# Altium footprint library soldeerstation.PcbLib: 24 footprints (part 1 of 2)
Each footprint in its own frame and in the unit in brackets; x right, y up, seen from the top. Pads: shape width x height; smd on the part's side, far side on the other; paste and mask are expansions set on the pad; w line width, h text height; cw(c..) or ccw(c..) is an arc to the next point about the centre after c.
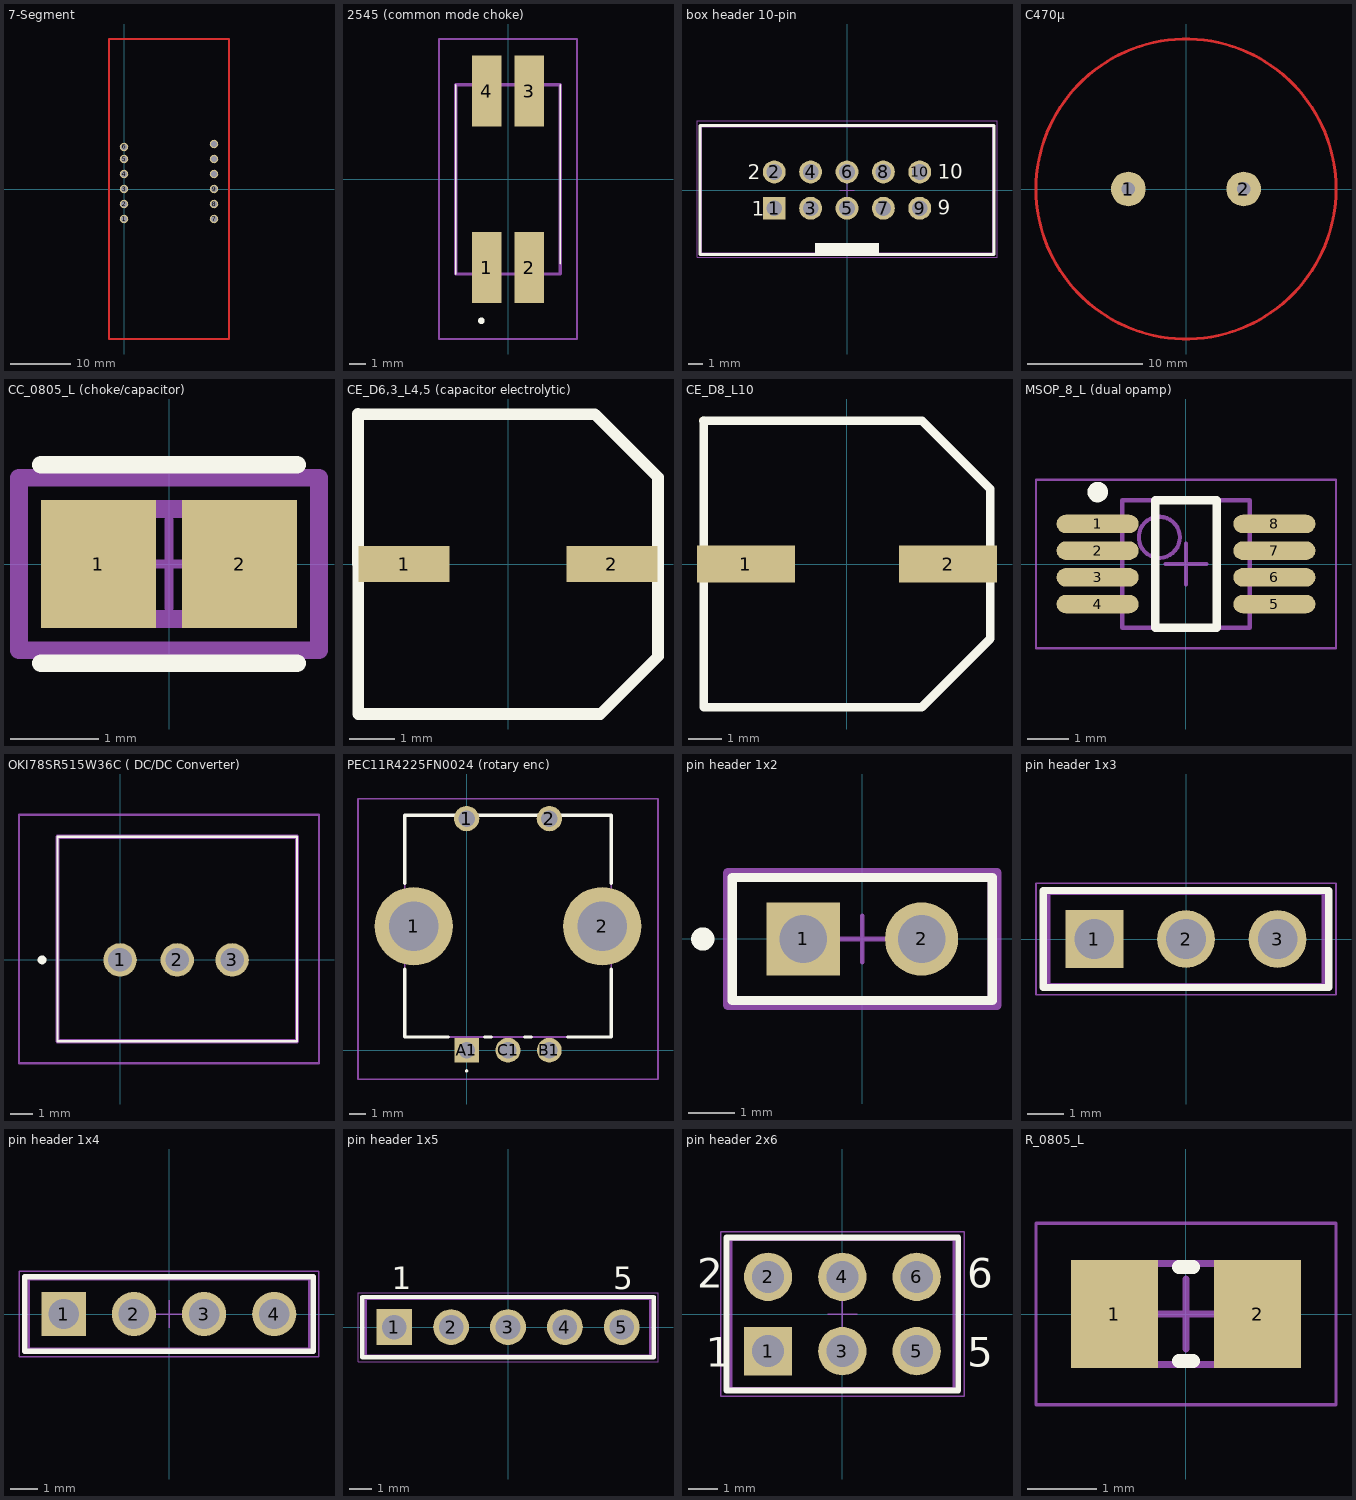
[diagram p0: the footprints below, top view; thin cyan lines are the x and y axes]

## 7-Segment [mm]
pads (12):
  round 1.425 hole 0.95: 1(0,-5) 2(0,-2.5) 3(0,0) 4(0,2.5) 5(0,5) 6(0,7) 7(15,-5) 8(15,-2.5) 9(15,0) 10(15,2.5) 11(15,5) 12(15,7.5)
Top Layer:
  lines w0.254: -2.5,-25 -2.5,15 -2.5,25 17.5,25 17.5,-25 -2.5,-25

## 2545 (common mode choke) [mm]
pads (4):
  rect 1.78x4.27 smd: 1(-1.27,-5.305) 2(1.27,-5.305) 3(1.27,5.305) 4(-1.27,5.305)
Top Overlay:
  lines w0.1: -3.15,-5.69 -3.15,5.69 ; 3.15,-5.08 3.15,5.69
  lines w0.2: -1.7,-8.5 cw(c-1.6,-8.5) -1.5,-8.5 cw(c-1.6,-8.5) -1.7,-8.5
Mechanical 13:
  lines w0.2: -3.15,-5.69 3.15,-5.69 3.15,5.69 -3.15,5.69 -3.15,-5.69
Mechanical 15:
  lines w0.1: -4.15,-9.6 4.15,-9.6 4.15,8.44 -4.15,8.44 -4.15,-9.6
3D body "CM2545X171R-10.stp": height 9.6, standoff 0, extent -3.15,-7.262 3.15,7.262

## box header 10-pin [mm] "10 pins, straight, gold plating"
height 9.1
pads (10):
  rect 1.6x1.6 hole 1.1: 1(-5.08,-1.27)
  round 1.6 hole 1.1: 2(-5.08,1.27) 3(-2.54,-1.27) 4(-2.54,1.27) 5(0,-1.27) 6(0,1.27) 7(2.54,-1.27) 8(2.54,1.27) 9(5.08,-1.27) 10(5.08,1.27)
Top Overlay:
  rectangle: -2.25,-4.5 2.25,-3.7
  lines w0.2: -10.28,-4.5 -10.28,4.5 10.28,4.5 10.28,-4.5 -10.28,-4.5
  text "9" at 6.34,-1.74 h1.02
  text "10" at 6.34,0.8 h1.02
  text "2" at -6.94,0.74 h1.02
  text "1" at -6.64,-1.8 h1.02
Mechanical 13:
  rectangle: -2.25,-4.425 2.25,-3.7
  lines w0.1: -10.18,-4.425 10.18,-4.425 10.18,4.425 -10.18,4.425 -10.18,-4.425
Mechanical 15:
  lines w0.05: -0.5,0 0.5,0 ; 0,-0.5 0,0.5 ; -10.48,-4.7 -10.48,4.85 10.48,4.85 10.48,-4.7 -10.48,-4.7
3D body "61201021621.stp": height 9.13, standoff -2.98, extent -10.18,-4.425 10.18,4.75

## C470µ [mm]
pads (2):
  round 3 hole 1.2: 1(-5,0) 2(5,0)
Top Layer:
  circle w0.254: c0,0 r13

## CC_0805_L (choke/capacitor) [mm]
pads (2):
  rect 1.305x1.456 smd paste+0 mask+0: 1(-0.801,0) 2(0.801,0)
Top Overlay:
  lines w0.2: -1.453,-1.128 1.453,-1.128 ; -1.453,1.128 1.453,1.128
Top 3D Body:
  lines w0.2: -1,-0.625 1,-0.625 1,0.625 -1,0.625 -1,-0.625
Top Courtyard:
  lines w0.2: -1.703,-0.978 1.703,-0.978 1.703,0.978 -1.703,0.978 -1.703,-0.978
Top Assembly:
  lines w0.2: -1.703,-0.978 1.703,-0.978 1.703,0.978 -1.703,0.978 -1.703,-0.978
  text ".Designator" at 0,0.188 h1
Top Component Center:
  lines w0.1: -0.5,0 0.5,0 ; 0,-0.5 0,0.5
3D body "Cap_KEMET_C0805C472J3HAC_eec.STEP": height 0.25, standoff 0, extent -1.703,-0.978 1.703,0.978

## CE_D6,3_L4,5 (capacitor electrolytic) [mm]
pads (2):
  rect 2x0.8 smd: 1(-2.286,0) 2(2.286,0)
Top Overlay:
  lines w0.254: -3.302,0.002 -3.3,0 -3.3,-3.3 2.034,-3.3 3.3,-2.034 3.3,1.907 1.907,3.3 0,3.3 -3.3,3.3 -3.302,3.302 -3.302,0.002

## CE_D8_L10 [mm]
pads (2):
  rect 2.9x1.1 smd: 1(-3,0) 2(3,0)
Top Layer:
  lines w0.254: -4.259,4.25 -4.25,4.241
Top Overlay:
  lines w0.254: -4.259,4.25 2.227,4.25 4.25,2.227 4.25,0 4.25,-2.218 2.218,-4.25 -4.25,-4.25 -4.25,4.241

## MSOP_8_L (dual opamp) [mm] "TSOP, 8-Leads, Body 3x3mm, Pitch 0.65mm, IPC Low Density"
height 1.1
pads (8):
  oval 2x0.45 smd: 1(-2.15,0.975) 2(-2.15,0.325) 3(-2.15,-0.325) 4(-2.15,-0.975) 5(2.15,-0.975) 6(2.15,-0.325) 7(2.15,0.325) 8(2.15,0.975)
Top Overlay:
  circle w0.25: c-2.15,1.75 r0.125
  lines w0.2: -0.75,-1.55 -0.75,1.55 0.75,1.55 0.75,-1.55 -0.75,-1.55
Mechanical 13:
  circle w0.1: c-0.65,0.65 r0.5
  lines w0.1: -1.55,-1.55 -1.55,1.55 1.55,1.55 1.55,-1.55 -1.55,-1.55
Mechanical 15:
  lines w0.05: -3.65,-2.05 -3.65,2.05 3.65,2.05 3.65,-2.05 -3.65,-2.05
  lines w0.1: -0.5,0 0.5,0 ; 0,-0.5 0,0.5
3D body: height 1.1, standoff 0, extent -1.55,-1.55 1.55,1.55

## OKI78SR515W36C ( DC/DC Converter) [mm]
pads (3):
  round 1.519 hole 1.08: 1(0,0) 2(2.6,0) 3(5.1,0)
Top Overlay:
  lines w0.1: -2.85,-3.7 8.05,-3.7 8.05,5.6 -2.85,5.6 -2.85,-3.7
  lines w0.3: -3.6,0 cw(c-3.55,0) -3.5,0 cw(c-3.55,0) -3.6,0
Mechanical 13:
  lines w0.2: -2.85,-3.7 8.05,-3.7 8.05,5.6 -2.85,5.6 -2.85,-3.7
Mechanical 15:
  lines w0.1: -4.6,-4.7 9.05,-4.7 9.05,6.6 -4.6,6.6 -4.6,-4.7
3D body "OKI-78SR-5_1.5-W36-C.stp": height 16.6, standoff -5, extent -2.85,-3.7 8.05,5.6

## PEC11R4225FN0024 (rotary enc) [mm]
pads (7):
  round 4.74 hole 3: 1(-3.2,7.5) 2(8.2,7.5)
  round 1.524 hole 1: 1(0,14) 2(5,14)
  rect 1.5x1.5 hole 1: A1(0,0)
  round 1.5 hole 1: B1(5,0) C1(2.5,0)
Top Overlay:
  lines w0.1: 0,-1.3 ccw(c0,-1.25) 0,-1.2 ccw(c0,-1.25) 0,-1.3
  lines w0.2: -3.75,4.9 -3.75,0.8 -1.1,0.8 ; -3.75,10.1 -3.75,14.2 8.75,14.2 8.75,10.1 ; 1.1,0.8 1.5,0.8 ; 3.5,0.8 3.9,0.8 ; 6.1,0.8 8.75,0.8 8.75,4.9
Mechanical 13:
  lines w0.1: -3.75,0.8 -3.75,14.2 8.75,14.2 8.75,0.8 -3.75,0.8
Mechanical 15:
  lines w0.1: -6.57,-1.75 -6.57,15.2 11.57,15.2 11.57,-1.75 -6.57,-1.75
3D body "PEC11R-4225F-N0024.stp": height 31.6, standoff -5, extent -4.668,-0.399 9.68,14.2

## pin header 1x2 [mm]
pads (2):
  rect 1.57x1.57 hole 1.02 paste-1000 mask+0: 1(-1.27,0)
  round 1.57 hole 1.02 paste-1000 mask+0: 2(1.27,0)
Top Overlay:
  circle w0.25: c-3.425,0 r0.125
  lines w0.2: -2.79,-1.32 -2.79,1.32 2.79,1.32 2.79,-1.32 -2.79,-1.32
Top 3D Body:
  lines w0.2: -2.79,-1.32 -2.79,1.32 2.79,1.32 2.79,-1.32 -2.79,-1.32
Top Courtyard:
  lines w0.2: -2.89,-1.42 -2.89,1.42 2.89,1.42 2.89,-1.42 -2.89,-1.42
Top Assembly:
  lines w0.2: -2.89,-1.42 -2.89,1.42 2.89,1.42 2.89,-1.42 -2.89,-1.42
  text ".Designator" at 0,0.188 h1
Top Component Center:
  lines w0.1: -0.5,0 0.5,0 ; 0,-0.5 0,0.5
3D body "Conn_Harwin_M20-9990246_eec.STEP": height 0.25, standoff 0, extent -2.89,-1.42 2.89,1.42

## pin header 1x3 [mm] "Pin Header, pitch 2.54 mm, THT, Vertical, single row, 3p"
height 8.54
pads (3):
  rect 1.6x1.6 hole 1.1: 1(-2.54,0)
  round 1.6 hole 1.1: 2(0,0) 3(2.54,0)
Top Overlay:
  lines w0.2: -3.96,-1.345 -3.96,1.345 3.96,1.345 3.96,-1.345 -3.96,-1.345
Mechanical 13:
  lines w0.1: -3.81,-1.27 3.81,-1.27 3.81,1.27 -3.81,1.27 -3.81,-1.27
Mechanical 15:
  lines w0.05: -0.5,0 0.5,0 ; 0,-0.5 0,0.5 ; -4.16,-1.545 4.16,-1.545 4.16,1.545 -4.16,1.545 -4.16,-1.545
3D body "61300311121.stp": height 8.57, standoff -2.97, extent -3.81,-1.27 3.81,1.27

## pin header 1x4 [mm] "Pin Header, pitch 2.54 mm, THT, Vertical, single row, 4p"
height 8.54
pads (4):
  rect 1.6x1.6 hole 1.1: 1(-3.81,0)
  round 1.6 hole 1.1: 2(-1.27,0) 3(1.27,0) 4(3.81,0)
Top Overlay:
  lines w0.2: -5.23,-1.345 -5.23,1.345 5.23,1.345 5.23,-1.345 -5.23,-1.345
Mechanical 13:
  lines w0.1: -5.08,-1.27 5.08,-1.27 5.08,1.27 -5.08,1.27 -5.08,-1.27
Mechanical 15:
  lines w0.05: -0.5,0 0.5,0 ; 0,-0.5 0,0.5 ; -5.43,-1.545 5.43,-1.545 5.43,1.545 -5.43,1.545 -5.43,-1.545
3D body "61300411121.stp": height 8.57, standoff -2.97, extent -5.08,-1.27 5.08,1.27

## pin header 1x5 [mm] "Pin Header, pitch 2.54 mm, THT, Vertical, single row, 5p"
height 8.54
pads (5):
  rect 1.6x1.6 hole 1.1: 1(-5.08,0)
  round 1.6 hole 1.1: 2(-2.54,0) 3(0,0) 4(2.54,0) 5(5.08,0)
Top Overlay:
  lines w0.2: -6.5,-1.345 -6.5,1.345 6.5,1.345 6.5,-1.345 -6.5,-1.345
  text "5" at 4.7,1.7 h1.02
  text "1" at -5.2,1.7 h1.02
Mechanical 13:
  lines w0.1: -6.35,-1.27 6.35,-1.27 6.35,1.27 -6.35,1.27 -6.35,-1.27
Mechanical 15:
  lines w0.05: -0.5,0 0.5,0 ; 0,-0.5 0,0.5 ; -6.7,-1.545 6.7,-1.545 6.7,1.545 -6.7,1.545 -6.7,-1.545
3D body "61300511121.stp": height 8.57, standoff -2.97, extent -6.35,-1.27 6.35,1.27

## pin header 2x6 [mm] "Pin Header, pitch 2.54 mm, THT, Vertical, dual row, 6p"
height 8.54
pads (6):
  rect 1.65x1.65 hole 1.1: 1(-2.54,-1.27)
  round 1.65 hole 1.1: 2(-2.54,1.27) 3(0,-1.27) 4(0,1.27) 5(2.54,-1.27) 6(2.54,1.27)
Top Overlay:
  lines w0.2: -3.96,-2.615 3.96,-2.615 3.96,2.615 -3.96,2.615 -3.96,-2.615
  text "6" at 4.27,0.9 h1.02
  text "5" at 4.27,-1.8 h1.02
  text "2" at -4.97,0.9 h1.02
  text "1" at -4.67,-1.8 h1.02
Mechanical 13:
  lines w0.1: -3.81,-2.54 3.81,-2.54 3.81,2.54 -3.81,2.54 -3.81,-2.54
Mechanical 15:
  lines w0.05: -0.5,0 0.5,0 ; 0,-0.5 0,0.5 ; -4.16,-2.815 -4.16,2.815 4.16,2.815 4.16,-2.815 -4.16,-2.815
3D body "61300621121.stp": height 8.59, standoff -2.95, extent -3.81,-2.54 3.81,2.54

## R_0805_L [mm] "Chip Resistor, 2-Leads, Body 2.00x1.25mm, IPC Low Density"
height 0.5
pads (2):
  rect 1.25x1.55 smd: 1(-1.025,0) 2(1.025,0)
Top Overlay:
  lines w0.2: -0.1,-0.675 0.1,-0.675 ; -0.1,0.675 0.1,0.675
Mechanical 13:
  lines w0.1: -1.1,-0.725 -1.1,0.725 1.1,0.725 1.1,-0.725 -1.1,-0.725
Mechanical 15:
  lines w0.05: -2.15,-1.3 -2.15,1.3 2.15,1.3 2.15,-1.3 -2.15,-1.3
  lines w0.1: -0.5,0 0.5,0 ; 0,-0.5 0,0.5
3D body: height 0.5, standoff 0, extent -0.8,-0.725 0.8,0.725
3D body: height 0.5, standoff 0, extent -1.1,-0.725 -0.8,0.725
3D body: height 0.5, standoff 0, extent 0.8,-0.725 1.1,0.725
